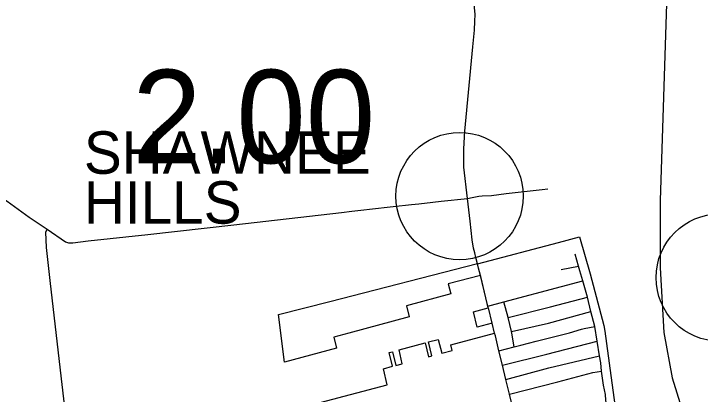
# Model space of a CAD drawing. Extents: x 1597222 to 1925846, y 496284 to 911751.
# Drawn here: x 1785084 to 1793175, y 788029 to 792512 of the extents above; entities that cross this region are included whole.
import ezdxf

# ---------------------------------------------------------------- set-up
doc = ezdxf.new("R2010")
doc.units = 0
for name, color, linetype in [('Default', 7, 'Continuous'), ('GM_X_City_Street', 7, 'Continuous'), ('GM_X_Corporation', 7, 'Continuous'), ('GM_X_Corporation_Text', 7, 'Continuous'), ('GM_X_County_Road', 7, 'Continuous'), ('GM_X_State_Route', 7, 'Continuous'), ('GM_X_Township', 7, 'Continuous'), ('GM_X_Township_Road', 7, 'Continuous')]:
    doc.layers.add(name, color=color, linetype=linetype)

msp = doc.modelspace()

# ---------------------------------------------------------------- linework, layer by layer
at = {"layer": 'Default'}
for centre in [(1790339.1, 790363.7), (1793404.1, 789403.3)]:
    msp.add_circle(centre, 750, dxfattribs=at)
at = {"layer": 'GM_X_City_Street'}
for points in [[(1791756.8, 789484.5), (1791740.9, 789538), (1791699.7, 789680.5)], [(1791535.6, 789499), (1791740.9, 789538)], [(1792238.8, 786727.6), (1792208.2, 786804.7), (1792200.3, 786859.2), (1792196.3, 786900.4), (1792199.2, 786985.8), (1792186.1, 787084.3), (1792137.2, 787434.5), (1792115, 787631.9), (1792086.9, 787787), (1792064, 787958.8), (1792057.7, 788025.6), (1792034.4, 788134.4), (1792012.1, 788299.1), (1792004.5, 788400.2), (1791987.7, 788482.9), (1791960.1, 788652.9), (1791931.9, 788826.6), (1791886.3, 789002.5), (1791844.8, 789173.7), (1791792.5, 789364.8), (1791756.8, 789484.5)], [(1790672.6, 789065.9), (1790860.7, 789117.8), (1791538.4, 789298.1), (1791792.5, 789364.8)], [(1790909.4, 788932.1), (1791410.5, 789060.1), (1791844.8, 789173.7)], [(1790954.1, 788748.5), (1790950.8, 788766.3), (1790909.4, 788932.1), (1790860.7, 789117.8)], [(1790950.8, 788766.3), (1791387, 788867.2), (1791886.3, 789002.5)], [(1791058.9, 788606.7), (1791242.8, 788652.7), (1791632.1, 788753.6), (1791776.2, 788795.7)], [(1791776.2, 788795.7), (1791805.2, 788804.1), (1791931.9, 788826.6)], [(1790983.3, 788587.8), (1790954.1, 788748.5)], [(1790802.9, 788538.5), (1790983.3, 788587.8), (1791058.9, 788606.7)], [(1790843.6, 788372.1), (1791366.1, 788501.2), (1791960.1, 788652.9)], [(1790885, 788204.3), (1791391.4, 788339.5), (1791987.7, 788482.9)], [(1790925.9, 788030.4), (1791495.7, 788175.3), (1791909.5, 788286.7), (1792012.1, 788299.1)]]:
    msp.add_lwpolyline(points, dxfattribs=at)
at = {"layer": 'GM_X_Corporation'}
msp.add_lwpolyline([(1788338.2, 787836.1), (1789485.1, 788139), (1789441.8, 788328.9), (1789549.6, 788357.9), (1789509, 788519.6), (1789546, 788529.6), (1789588, 788368.2), (1789663.1, 788388.4), (1789625, 788551), (1789933.7, 788633.4), (1789973.1, 788471), (1790010.7, 788480.9), (1789972.2, 788645), (1790087.5, 788675.2), (1790127.5, 788511.5), (1790250.6, 788544.7), (1790234.1, 788611.6), (1790752, 788749.1), (1790722.9, 788865.1), (1790547.2, 788818.3), (1790502.8, 789000.9), (1790677.2, 789047.4), (1790648.1, 789166.5), (1790584.1, 789428.3), (1790204.3, 789331.7), (1790234.8, 789210.2), (1789713.6, 789072.4), (1789746, 788941.7), (1789031.9, 788748), (1788856.8, 788701.4), (1788889.4, 788571.4), (1788273.7, 788407.5), (1788203.5, 788966.9), (1788809.5, 789121.7), (1790549.8, 789569.1), (1790550.6, 789565.7), (1791504.7, 789818.5), (1791752.8, 789884.2), (1791875.7, 789446.6), (1792038.1, 788840.2), (1792049.2, 788770.3), (1792122, 788248.2), (1792318.8, 786813.4)], dxfattribs=at)
at = {"layer": 'GM_X_County_Road'}
for points in [[(1784637.9, 790333.5), (1784843.3, 790356.7), (1784876.6, 790356.8), (1784894.3, 790354.6), (1784911.7, 790350.8), (1784928.7, 790345.4), (1784960.9, 790330.3), (1785005.7, 790303.2), (1785267.5, 790117.1), (1785478.8, 789971.9)], [(1785478.8, 789971.9), (1785695.1, 789825.6), (1785728.1, 789813.2), (1785781.6, 789813.2), (1785960.9, 789838), (1786665.4, 789910.1), (1787678.6, 790024.5), (1788948.6, 790172), (1789067.8, 790185.5), (1789208.7, 790202), (1789277.1, 790209.3), (1789555.4, 790241.6), (1789772.6, 790264.8), (1789859.7, 790273.7), (1790024.6, 790292.6), (1790121, 790303), (1790431.8, 790335.3)]]:
    msp.add_lwpolyline(points, dxfattribs=at)
at = {"layer": 'GM_X_State_Route'}
for points in [[(1790431.8, 790335.3), (1790390.2, 790705.8), (1790390.2, 790919.6), (1790398.9, 791127.5), (1790495.5, 792123.3), (1790513.6, 792320.2), (1790520, 792424), (1790520.9, 792501.2), (1790515.8, 792584.3), (1790506.6, 792651.8), (1790486.6, 792747.6), (1790461.5, 792837.7), (1790398.6, 793056.3), (1790334, 793268), (1790306.9, 793367.3)], [(1790550.6, 789565.7), (1790530.2, 789639.9), (1790517.2, 789695.6), (1790504.1, 789749.9), (1790487.2, 789846.7), (1790462.5, 790066.5), (1790431.8, 790335.3)], [(1790562.8, 789515.8), (1790550.6, 789565.7)], [(1790587.1, 789416), (1790584.1, 789428.3), (1790562.8, 789515.8)], [(1790677.6, 789045.8), (1790677.2, 789047.4), (1790672.6, 789065.9), (1790648.1, 789166.5), (1790587.1, 789416)], [(1790722.9, 788865.1), (1790677.6, 789045.8)], [(1790759.9, 788716.4), (1790752, 788749.1), (1790722.9, 788865.1)], [(1791422.4, 786035.2), (1791393.4, 786137.9), (1791353.4, 786320), (1791314, 786497.7), (1791263.5, 786674.5), (1791219.3, 786844.9), (1791176.3, 787013.2), (1791134.7, 787187.2), (1791096.7, 787335.3), (1791095.3, 787340.7), (1791051, 787519.6), (1791011.5, 787684.8), (1791010, 787691.1), (1790965.8, 787870.2), (1790925.9, 788030.4), (1790885, 788204.3), (1790843.6, 788372.1), (1790802.9, 788538.5), (1790759.9, 788716.4)]]:
    msp.add_lwpolyline(points, dxfattribs=at)
at = {"layer": 'GM_X_Township'}
msp.add_lwpolyline([(1792782.7, 792752.7), (1792702.3, 790313.3), (1792702.4, 789519.4), (1792744.6, 788755.4), (1792845.1, 788222), (1793027.9, 787628.5), (1793570.2, 786064.3), (1793601, 785958), (1793696.8, 785627.1), (1793702.8, 785362.4), (1793622.7, 785191.4), (1793510.1, 784951.2), (1793648.7, 784141), (1793768, 783639.7), (1794156.9, 782686.5), (1794234.9, 782300.4), (1794421.7, 781745.8), (1794530.5, 781464.8), (1794889.4, 781165.8), (1795007.3, 780959.2), (1795116.1, 780658.3), (1795136, 780422.6), (1795094.9, 780091.3)], dxfattribs=at)
at = {"layer": 'GM_X_Township_Road'}
for points in [[(1790431.8, 790335.3), (1790487.9, 790347.7), (1790565.5, 790361), (1790604.7, 790367), (1790715.3, 790372.4), (1790889.2, 790392.2), (1791311.7, 790442.2), (1791379.9, 790447.1)], [(1786081.4, 784452.9), (1786079.1, 784473.7), (1786015.3, 785023.9), (1786008.5, 785081.3), (1786001.8, 785154), (1785992.2, 785223), (1785983.4, 785308.6), (1785963.6, 785466.2), (1785835.9, 786586.8), (1785811.7, 786799), (1785754.3, 787294.9), (1785610.6, 788517.6), (1785547.6, 789062.7), (1785517.1, 789335), (1785468.5, 789757.6), (1785460.3, 789939), (1785478.8, 789971.9)]]:
    msp.add_lwpolyline(points, dxfattribs=at)

# ---------------------------------------------------------------- texts
at = {"layer": 'Default'}
msp.add_text('2.00', height=1100, dxfattribs=at).set_placement((1786480.6, 790751.1))
at = {"layer": 'GM_X_Corporation_Text'}
for s, p in [('SHAWNEE', (1785910.5, 790626.6)), ('HILLS', (1785910.5, 790039))]:
    msp.add_text(s, height=500, rotation=0.00001, dxfattribs=at).set_placement(p)

doc.saveas('drawing.dxf')
